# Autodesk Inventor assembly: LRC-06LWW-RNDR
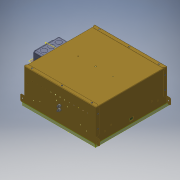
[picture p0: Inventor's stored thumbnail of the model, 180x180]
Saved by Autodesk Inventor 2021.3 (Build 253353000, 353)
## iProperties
Part Number: LRC-06LWW-RNDR
Document SubType Name: Assembly
Designer: JChurch
Author: JChurch
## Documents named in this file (5)
- X:\Revit Files\0000-Un-Zipped\COB\LRC-06LWW-RND\LRC-06LWW-RNDR.iam
- X:\INVENTOR\830\830399-00-00.ipt
- X:\INVENTOR\881\881088-00-00.iam
- X:\INVENTOR\700\700458-00-XX.iam
- X:\INVENTOR\KIRLIN_ENG\725\725075-02-00.ipt
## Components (4 placed, 4 different names)
1. 830399-00-00:1 — Mate:1, Mate:2, Mate:3, Mate:4, Tangent:1, Angle:1, Insert:1, Mate:5
2. 881088-00-00:1 [sub-assembly] — Mate:4, Tangent:1, Angle:1
3. 700458-00-XX:1 [sub-assembly] — Insert:1, Mate:5, Mate:6, Mate:7
4. 725075-02-00:1 — Mate:6, Mate:7
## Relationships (10: Mate 7, Tangent 1, Angle 1, Insert 1)
- Mate:1: 830399-00-00:1
- Mate:2: 830399-00-00:1
- Mate:3: 830399-00-00:1
- Mate:4: 830399-00-00:1 ↔ 881088-00-00:1
- Tangent:1: 830399-00-00:1 ↔ 881088-00-00:1
- Angle:1: 830399-00-00:1 ↔ 881088-00-00:1
- Insert:1: 830399-00-00:1 ↔ 700458-00-XX:1
- Mate:5: 830399-00-00:1 ↔ 700458-00-XX:1
- Mate:6: 700458-00-XX:1 ↔ 725075-02-00:1
- Mate:7: 700458-00-XX:1 ↔ 725075-02-00:1
